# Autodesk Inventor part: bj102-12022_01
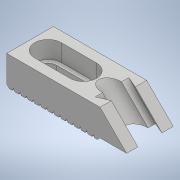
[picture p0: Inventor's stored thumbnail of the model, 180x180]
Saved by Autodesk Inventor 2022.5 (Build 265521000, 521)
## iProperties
Part Number: bj102-12022_01
Material: 一般
Document SubType Name: Modeling
Designer: ImaoCorp
Density: 1 g/cm^3
Appearance: 既定
Author: ImaoCorp
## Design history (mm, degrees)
feature "bj102-12022_01"
node "ソリッド1"
